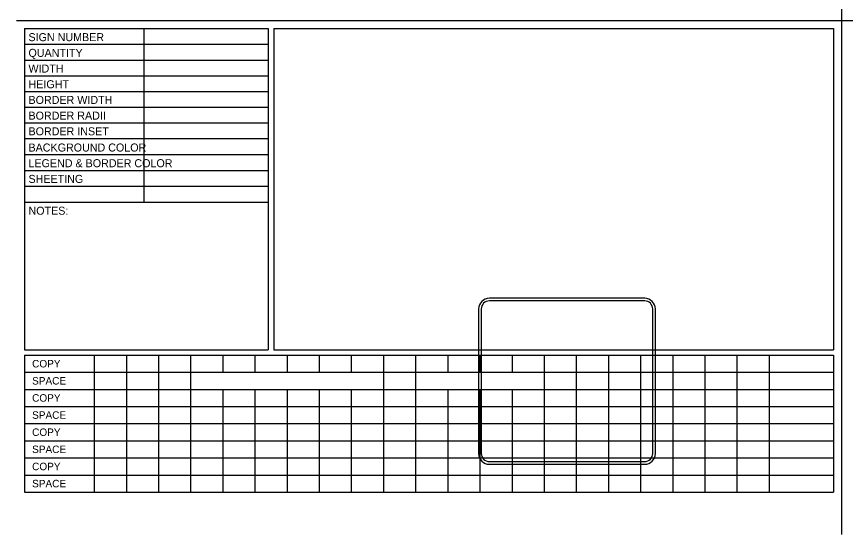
# Model space of a CAD drawing. Extents: x 10268197 to 10268511, y 2141503 to 2142677.
# Drawn here: x 10268317.7 to 10268395.1, y 2142274.3 to 2142322.7 of the extents above; entities that cross this region are included whole.
import ezdxf

# ---------------------------------------------------------------- set-up
doc = ezdxf.new("R2010")
doc.units = 0
for name, color, linetype in [('GSOutline', 7, 'Continuous'), ('SheetBorder_dp', 7, 'Continuous'), ('SumBoxLines_dp', 7, 'Continuous'), ('SumBoxLinesMin_dp', 7, 'Continuous'), ('TextMisc', 7, 'Continuous')]:
    doc.layers.add(name, color=color, linetype=linetype)

msp = doc.modelspace()

# ---------------------------------------------------------------- linework, layer by layer
at = {"layer": 'GSOutline'}
for p, q in [((10268376.364, 2142296.34), (10268361.863, 2142296.34)), ((10268376.364, 2142296.09), (10268361.863, 2142296.09)), ((10268360.863, 2142295.34), (10268360.863, 2142281.839)), ((10268361.113, 2142295.34), (10268361.113, 2142281.839)), ((10268377.114, 2142281.839), (10268377.114, 2142295.34)), ((10268377.364, 2142281.839), (10268377.364, 2142295.34)), ((10268361.863, 2142281.089), (10268376.364, 2142281.089)), ((10268361.863, 2142280.839), (10268376.364, 2142280.839))]:
    msp.add_line(p, q, dxfattribs=at)
for centre, radius, start, end in [((10268361.863, 2142295.34), 1, 90, 180), ((10268361.863, 2142295.34), 0.75, 90, 180), ((10268376.364, 2142295.34), 1, 0, 90), ((10268376.364, 2142295.34), 0.75, 0, 90), ((10268361.863, 2142281.839), 1, 180, 270), ((10268361.863, 2142281.839), 0.75, 180, 270), ((10268376.364, 2142281.839), 1, 270, 0), ((10268376.364, 2142281.839), 0.75, 270, 0)]:
    msp.add_arc(centre, radius, start, end, dxfattribs=at)
at = {"layer": 'SheetBorder_dp'}
for p, q in [((10268394.73, 2142370.281), (10268394.73, 2142274.281)), ((10268317.73, 2142322.281), (10268471.73, 2142322.281))]:
    msp.add_line(p, q, dxfattribs=at)
at = {"layer": 'SumBoxLines_dp'}
for p, q in [((10268318.48, 2142321.531), (10268318.48, 2142291.531)), ((10268318.48, 2142321.531), (10268341.23, 2142321.531)), ((10268329.598, 2142321.527), (10268329.598, 2142305.307)), ((10268341.23, 2142321.531), (10268341.23, 2142291.531)), ((10268341.73, 2142321.531), (10268341.73, 2142291.531)), ((10268341.73, 2142321.531), (10268393.98, 2142321.531)), ((10268393.98, 2142321.531), (10268393.98, 2142291.531)), ((10268318.48, 2142320.065), (10268341.23, 2142320.065)), ((10268318.48, 2142318.589), (10268341.23, 2142318.589)), ((10268318.48, 2142317.124), (10268341.23, 2142317.124)), ((10268318.48, 2142315.658), (10268341.23, 2142315.658)), ((10268318.48, 2142314.192), (10268341.23, 2142314.192)), ((10268318.48, 2142312.726), (10268341.23, 2142312.726)), ((10268318.48, 2142311.26), (10268341.23, 2142311.26)), ((10268318.48, 2142309.785), (10268341.23, 2142309.785)), ((10268318.48, 2142308.28), (10268341.23, 2142308.28)), ((10268318.48, 2142306.804), (10268341.23, 2142306.804)), ((10268318.479, 2142305.307), (10268341.23, 2142305.307)), ((10268318.48, 2142291.531), (10268341.23, 2142291.531)), ((10268341.73, 2142291.531), (10268393.98, 2142291.531)), ((10268318.48, 2142291.031), (10268393.98, 2142291.031)), ((10268318.48, 2142291.031), (10268318.48, 2142278.231)), ((10268324.98, 2142291.031), (10268324.98, 2142278.231)), ((10268327.98, 2142291.031), (10268327.98, 2142278.231)), ((10268330.98, 2142291.031), (10268330.98, 2142287.831)), ((10268333.98, 2142291.031), (10268333.98, 2142287.831)), ((10268336.98, 2142291.031), (10268336.98, 2142289.431)), ((10268339.98, 2142291.031), (10268339.98, 2142289.431)), ((10268342.98, 2142291.031), (10268342.98, 2142289.431)), ((10268345.98, 2142291.031), (10268345.98, 2142289.431)), ((10268348.98, 2142291.031), (10268348.98, 2142289.431)), ((10268351.98, 2142291.031), (10268351.98, 2142287.831)), ((10268354.98, 2142291.031), (10268354.98, 2142287.831)), ((10268357.98, 2142291.031), (10268357.98, 2142289.431)), ((10268360.98, 2142291.031), (10268360.98, 2142289.431)), ((10268363.98, 2142291.031), (10268363.98, 2142289.431)), ((10268366.98, 2142291.031), (10268366.98, 2142287.831)), ((10268369.98, 2142291.031), (10268369.98, 2142289.431)), ((10268372.98, 2142291.031), (10268372.98, 2142289.431)), ((10268375.98, 2142291.031), (10268375.98, 2142289.431)), ((10268378.98, 2142291.031), (10268378.98, 2142289.431)), ((10268381.98, 2142291.031), (10268381.98, 2142289.431)), ((10268384.98, 2142291.031), (10268384.98, 2142289.431)), ((10268387.98, 2142291.031), (10268387.98, 2142289.431)), ((10268393.98, 2142291.031), (10268393.98, 2142278.231)), ((10268366.98, 2142289.431), (10268366.98, 2142283.031)), ((10268369.98, 2142289.431), (10268369.98, 2142283.031)), ((10268372.98, 2142289.431), (10268372.98, 2142278.231)), ((10268375.98, 2142289.431), (10268375.98, 2142278.231)), ((10268378.98, 2142289.431), (10268378.98, 2142283.031)), ((10268381.98, 2142289.431), (10268381.98, 2142283.031)), ((10268384.98, 2142289.431), (10268384.98, 2142283.031)), ((10268387.98, 2142289.431), (10268387.98, 2142278.231)), ((10268318.48, 2142287.831), (10268393.98, 2142287.831)), ((10268330.98, 2142287.831), (10268330.98, 2142281.431)), ((10268333.98, 2142287.831), (10268333.98, 2142281.431)), ((10268336.98, 2142287.831), (10268336.98, 2142281.431)), ((10268339.98, 2142287.831), (10268339.98, 2142284.631)), ((10268342.98, 2142287.831), (10268342.98, 2142284.631)), ((10268345.98, 2142287.831), (10268345.98, 2142284.631)), ((10268348.98, 2142287.831), (10268348.98, 2142284.631)), ((10268351.98, 2142287.831), (10268351.98, 2142284.631)), ((10268354.98, 2142287.831), (10268354.98, 2142283.031)), ((10268357.98, 2142287.831), (10268357.98, 2142283.031)), ((10268360.98, 2142287.831), (10268360.98, 2142281.431)), ((10268363.98, 2142287.831), (10268363.98, 2142281.431)), ((10268318.48, 2142284.631), (10268393.98, 2142284.631)), ((10268339.98, 2142284.631), (10268339.98, 2142281.431)), ((10268342.98, 2142284.631), (10268342.98, 2142281.431)), ((10268345.98, 2142284.631), (10268345.98, 2142281.431)), ((10268348.98, 2142284.631), (10268348.98, 2142281.431)), ((10268351.98, 2142284.631), (10268351.98, 2142281.431)), ((10268354.98, 2142283.031), (10268354.98, 2142278.231)), ((10268357.98, 2142283.031), (10268357.98, 2142278.231)), ((10268366.98, 2142283.031), (10268366.98, 2142278.231)), ((10268369.98, 2142283.031), (10268369.98, 2142278.231)), ((10268378.98, 2142283.031), (10268378.98, 2142278.231)), ((10268381.98, 2142283.031), (10268381.98, 2142278.231)), ((10268384.98, 2142283.031), (10268384.98, 2142278.231)), ((10268318.48, 2142281.431), (10268393.98, 2142281.431)), ((10268330.98, 2142281.431), (10268330.98, 2142278.231)), ((10268333.98, 2142281.431), (10268333.98, 2142278.231)), ((10268336.98, 2142281.431), (10268336.98, 2142278.231)), ((10268339.98, 2142281.431), (10268339.98, 2142278.231)), ((10268342.98, 2142281.431), (10268342.98, 2142278.231)), ((10268345.98, 2142281.431), (10268345.98, 2142278.231)), ((10268348.98, 2142281.431), (10268348.98, 2142278.231)), ((10268351.98, 2142281.431), (10268351.98, 2142278.231)), ((10268360.98, 2142281.431), (10268360.98, 2142278.231)), ((10268363.98, 2142281.431), (10268363.98, 2142278.231)), ((10268318.48, 2142278.231), (10268393.98, 2142278.231))]:
    msp.add_line(p, q, dxfattribs=at)
at = {"layer": 'SumBoxLinesMin_dp'}
for p, q in [((10268318.48, 2142289.431), (10268393.98, 2142289.431)), ((10268318.48, 2142286.231), (10268393.98, 2142286.231)), ((10268318.48, 2142283.031), (10268393.98, 2142283.031)), ((10268318.48, 2142279.831), (10268393.98, 2142279.831))]:
    msp.add_line(p, q, dxfattribs=at)

# ---------------------------------------------------------------- texts
at = {"layer": 'TextMisc'}
for s, height, p in [('SIGN NUMBER', 0.74756, (10268318.842, 2142320.358)), ('QUANTITY', 0.7476, (10268318.842, 2142318.892)), ('WIDTH', 0.7476, (10268318.842, 2142317.427)), ('HEIGHT', 0.7476, (10268318.842, 2142315.961)), ('BORDER WIDTH', 0.74756, (10268318.842, 2142314.495)), ('BORDER RADII', 0.74756, (10268318.842, 2142313.029)), ('BORDER INSET', 0.74756, (10268318.842, 2142311.563)), ('BACKGROUND COLOR', 0.74756, (10268318.842, 2142310.049)), ('LEGEND & BORDER COLOR', 0.74756, (10268318.842, 2142308.583)), ('SHEETING', 0.7476, (10268318.842, 2142307.117)), ('NOTES:', 0.7476, (10268318.842, 2142304.146)), ('COPY', 0.7, (10268319.18, 2142289.881)), ('SPACE', 0.7, (10268319.18, 2142288.281)), ('COPY', 0.7, (10268319.18, 2142286.681)), ('SPACE', 0.7, (10268319.18, 2142285.081)), ('COPY', 0.7, (10268319.18, 2142283.481)), ('SPACE', 0.7, (10268319.18, 2142281.881)), ('COPY', 0.7, (10268319.18, 2142280.281)), ('SPACE', 0.7, (10268319.18, 2142278.681))]:
    msp.add_text(s, height=height, dxfattribs=at).set_placement(p)

doc.saveas('drawing.dxf')
